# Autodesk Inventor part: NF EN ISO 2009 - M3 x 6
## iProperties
Created: 2007-08
Part Number: NF EN ISO 2009 - M3 x 6
Material: Stahl, weich, unlegiert
Description: Senkschraube
Vendor: Autodesk Inc.
Document SubType Name: Modeling
Standard: ISO 2009
Designer: Ulrich
Standards Organization: AFNOR
Language: de-DE
Size Designation: M3 x 6
Categories: <MemberInstance Version="R10.0.0"><Categories><Category DisplayName="Schrauben" InternalName="e4da775c-781d-43d5-af7c-5136215cf5a6" Mnemonic="FSTN"><Category Di
Author: Ulrich
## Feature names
1. Körper [Revolution]
2. Loch [Extrusion]
3. Fase1 [Chamfer]
